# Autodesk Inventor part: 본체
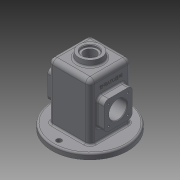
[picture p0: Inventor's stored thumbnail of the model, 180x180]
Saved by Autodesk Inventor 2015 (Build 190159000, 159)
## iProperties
Created: 2021-08
Part Number: 본체
Material: 일반
Document SubType Name: Modeling
Designer: 104-00
Density: 1 g/cm^3
Appearance: 기본값
Author: 104-00
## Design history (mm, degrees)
sketch "스케치1"
  geometry: C1 r 67 at (0, 0); 1 further point
  constraints: 1 centre point, 1 coincident
  dimensions: "d0" = 134 diameter of C1
extrude "돌출1" new body sketch "스케치1" distance "d1" = 10; taper "d2" = 0 deg
sketch "스케치2"
  geometry: L1 (-37, -37)-(37, -37); L2 (37, -37)-(37, 37); L3 (37, 37)-(-37, 37); L4 (-37, 37)-(-37, -37); L5 (-37, -37)-(37, 37); L6 (37, -37)-(-37, 37); C1 r 67 at (0, 0) reference; 2 further points
  constraints: 12 end point, 3 midpoint, 2 parallel, 1 coincident, 1 horizontal, 1 perpendicular
  dimensions: "d3" = 74 distance of L2.end L3.end; "d4" = 74 distance of L3.end L1.start
extrude "돌출2" join sketch "스케치2" distance "d5" = 100; taper "d6" = 0 deg
fillet "모깎기5" dims "d19" = 8
fillet "모깎기6" dims "d20" = 8
sketch "스케치5"
  geometry: L1 (32, 32)-(-32, 32); L2 (-32, 32)-(-32, -32); L3 (-32, -32)-(32, -32); L4 (32, -32)-(32, 32); L5 (32, 32)-(-32, -32); L6 (-32, 32)-(32, -32); C1 r 67 at (0, 0) reference; 1 further point
  constraints: 12 end point, 2 midpoint, 2 parallel, 1 horizontal, 1 perpendicular
  dimensions: "d21" = 64 distance of L2.end L3.end; "d22" = 64 distance of L3.end L1.start
extrude "돌출4" cut sketch "스케치5" distance "d23" = 105; taper "d24" = 0 deg
fillet "모깎기7" dims "d25" = 3
fillet "모깎기8" dims "d26" = 3
sketch "스케치6"
  geometry: L1 (20, 54)-(70, 54); L2 (70, 54)-(70, 4); L3 (70, 4)-(20, 4); L4 (20, 4)-(20, 54); L5 (20, 54)-(70, 4); L6 (70, 54)-(20, 4); L7 (-10, 96)-(-10, -38) reference; L8 (92, 66)-(0, 66) reference; 2 further points
  constraints: 12 end point, 2 midpoint, 2 parallel, 1 horizontal, 1 perpendicular
  dimensions: "d27" = 55 distance from line of L7 point (45, 29); "d28" = 37 distance from line of L8 point (45, 29); "d29" = 50 distance of L1.end L2.end; "d30" = 50 distance of L2.end L3.end
extrude "돌출5" join sketch "스케치6" distance "d31" = 13; taper "d32" = 0 deg
sketch "스케치7"
  geometry: L1 (-102, 66)-(-10, 66) reference; L2 (-80, 54)-(-30, 54) reference; L3 (-30, 54)-(-30, 4) reference; L4 (-30, 4)-(-80, 4) reference; L5 (-80, 4)-(-80, 54) reference; L6 (-10, 87.864)-(0, 87.864) reference; L7 (0, 87.864)-(0, 58) reference; L8 (-102, 58)-(0, 58) reference; L9 (-102, 0)-(-102, 58) reference; L10 (-102, 0)-(0, 0) reference; L11 (0, 0)-(0, -29.864) reference; L12 (0, -29.864)-(-10, -29.864) reference; L13 (-10, -29.864)-(-10, -7.416) reference; L14 (-10, -7.416)-(-102, -7.416) reference; L15 (-109.416, 0)-(-109.416, 58) reference; L16 (-102, 65.416)-(-10, 65.416) reference; L17 (-10, 65.416)-(-10, 87.864) reference; L18 (0, 58)-(0, 0) reference; C1 r 25 at (-55, 29); A1 r 7.416 centre (-102, 0) between (-109.416, 0) and (-102, -7.416) reference; A2 r 7.416 centre (-102, 58) between (-102, 65.416) and (-109.416, 58) reference; 1 further point
  constraints: 1 centre point
  dimensions: "d33" = 50 diameter of C1; "d34" = 55 distance from line of L7 C1.centre; "d89" = 37 distance from line of C1.centre L1
extrude "돌출6" join sketch "스케치7" distance "d36" = 7; taper "d37" = -20 deg
sketch "스케치8"
  geometry: C1 r 25 at (45, 29) reference; 2 further points
  constraints: 1 coincident
hole "구멍1" sketch "스케치8" at (45, 29) diameter "d38" = 32; stored, may be unused: countersink angle "d42" = 90 deg, drill point angle "d44" = 118 deg; dims "d39" = 6, "d40" = 4, "d41" = 2, "d43" = 8
sketch "스케치9"
  geometry: C1 r 67 at (0, 0) reference; 3 further points
  constraints: 2 vertical alignment
  dimensions: "d45" = 55 distance of C1.centre point (0, 55); "d46" = 55 distance of C1.centre point (0, -55)
hole "구멍2" sketch "스케치9" at (0, 55), (0, -55) diameter "d47" = 9; stored, may be unused: countersink angle "d51" = 90 deg, drill point angle "d53" = 118 deg; dims "d48" = 6, "d49" = 4, "d50" = 2, "d52" = 8
sketch "스케치10" dims "d23" = 105
  geometry: C1 r 16 at (25, 25) reference; 2 further points
  dimensions: "d54" = 17 horizontal distance of point (8, 42) C1.centre; "d55" = 17 horizontal distance of C1.centre point (8, 42)
hole "구멍3" sketch "스케치10" at (8, 42) diameter "d56" = 3.242; stored, may be unused: countersink angle "d60" = 90 deg, drill point angle "d62" = 118 deg; dims "d23" = 105, "d57" = 8, "d58" = 4, "d59" = 2, "d61" = 10
sketch "스케치11"
  geometry: C1 r 20 at (0, 0); 1 further point
  constraints: 1 centre point, 1 coincident
  dimensions: "d69" = 40 diameter of C1
extrude "돌출7" join sketch "스케치11" distance "d70" = 10; taper "d71" = 0 deg
feature "면 기울기1" dims angle "d90" = 6 deg
sketch "스케치12"
  geometry: C1 r 20 at (0, 0) reference
hole "구멍4" sketch "스케치12" at (0, 0) diameter "d72" = 21; stored, may be unused: countersink angle "d76" = 90 deg, drill point angle "d78" = 118 deg; dims "d73" = 8, "d74" = 28, "d75" = 4, "d77" = 20
sketch "스케치13"
  geometry: L1 (-110, 49)-(-110, 9) reference; L2 (-92, -8)-(0, -8) reference; 2 further points
  constraints: 1 other
  dimensions: "d80" = 37 distance from line of L2 point (-82, 29); "d91" = 28 distance from line of point (-82, 29) L1
feature "엠보싱2" sketch "스케치13" dims "d92" = 0.5, "d93" = 0
fillet "모깎기9" dims "d83" = 8
fillet "모깎기10" dims "d84" = 8
fillet "모깎기11" dims "d85" = 3
chamfer "모따기1" distance "d86" = 1; stored, may be unused: second distance "d87" = 2, angle "d88" = 45 deg
node "솔리드1"
mirror "대칭1"
pattern_linear "직사각형 패턴1" dims "d65" = 34, "d68" = 34
mirror "대칭2"
node "투영된 루프1"
node "절단 모서리 투영1"
